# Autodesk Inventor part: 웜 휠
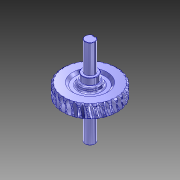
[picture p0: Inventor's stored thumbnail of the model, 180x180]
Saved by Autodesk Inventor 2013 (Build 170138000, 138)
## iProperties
Created: 2013-01
Part Number: 웜 휠
Material: 일반
Document SubType Name: Modeling
Designer: 한국산업디자인학원[gmhk.co.kr]
Categories: <?xml version="1.0" encoding="UTF-16"?> <MemberInstance><Categories><FamilyTemplate><FamilyTemplateParameter ValueType="xs:double" Id="1" ObjectReferenceKey="da
Density: 7.87 g/cm^3
Mass: 6989.44 g
Surface Area: 1041.74 cm^2
Volume: 888.112 cm^3
CustomPartVersion: 1
Author: 한국산업디자인학원[gmhk.co.kr]
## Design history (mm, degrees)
body "Solid1"
node "톱니 평면"
sketch "기본 본체 스케치"
  geometry: L1 (0, -14)-(0, 14) reference; L2 (0, 20)-(77.639, 20); L3 (77.639, 20)-(82.5, 15.652); L4 (-10, 0)-(60, 0) reference; L5 (82.5, 15.652)-(82.5, -15.652); L6 (0, -20)-(77.639, -20); L7 (0, 20)-(0, -20); L8 (77.639, -20)-(82.5, -15.652); C1 r 20 at (100, 0)
  constraints: 14 end point, 3 symmetric about line, 2 perpendicular, 2 point on line, 1 centre point, 1 collinear
  dimensions: "d50" = 41.8103 deg angle of L3 L2 (= da_fi); "d87" = 165 diameter of L5 L1 (= da_dae); "d89" = 40 diameter of C1 (= 2 x da_aw - da_da); "d92" = 40 distance of L2.start L6.start (= da_b); "d93" = 100 distance from line of C1.centre L7 (= da_aw)
revolve "기본 본체" stored, may be unused: angle "d35" = 90 deg
revolve "기본 본체2" stored, may be unused: angle "d90" = 90 deg
workplane "Work Plane13"
revolve "톱니" stored, may be unused: angle "d43" = 90 deg
pattern_circular "톱니 패턴" dims angle "d46" = 360 deg
workplane "Work Plane14"
workplane "Work Plane15"
revolve "회전6" stored, may be unused: angle "d97" = 90 deg
revolve "회전7" stored, may be unused: angle "d104" = 90 deg
fillet "모깎기1" dims "d105" = 5
chamfer "모따기1" distance "d106" = 1; stored, may be unused: second distance "d107" = 2, angle "d108" = 45 deg
node "작업 평면16"
sketch "스케치11"
  geometry: L1 (-14, 43)-(14, 43) reference; L2 (4, 43)-(4, 22); L3 (-4, 22)-(-4, 43); A1 r 4 centre (0, 22) between (-4, 22) and (4, 22); 2 further points
  constraints: 4 end point, 2 perpendicular, 2 point on circle, 2 point on line, 2 tangent, 1 centre point, 1 midpoint, 1 vertical alignment
  dimensions: "d109" = 8 distance between parallel lines of L2 L3; "d110" = 25 dimension on A1 L1
extrude "돌출1" cut sketch "스케치11" distance "d111" = 4; taper "d112" = 0 deg
mirror "대칭1"
sketch "톱니 스케치"
  geometry: L1 (10, 5.301)-(10, -5.301) reference; L2 (-32.842, 0)-(-12.948, 0) reference; L3 (-90, 6.896)-(-90, -6.896); L4 (-90, -6.896)-(-71, -6.896); L5 (-71, -6.896)-(-59, -2.529); L6 (-59, -2.529)-(-59, 0); L7 (-59, 2.529)-(-71, 6.896); L8 (-71, 6.896)-(-90, 6.896); L9 (-59, 2.529)-(-59, 0); L10 (-65, 0)-(-65, -4.712)
  constraints: 16 end point, 4 perpendicular, 3 equal length, 2 point on line, 1 midpoint, 1 parallel, 1 vertical
  dimensions: "d38" = 100 distance between parallel lines of L1 L3 (= da_aw); "d39" = 20 deg angle of L7 L8 (= da_alfat); "d40" = 19 distance of L7.end L3.start (= 0.5 x da_df1); "d41" = 25 distance between parallel lines of L3 L10 (= 0.5 x da_d1); "d42" = 4.71239 distance of L10.start L10.end (= 0.3 x da_px)
sketch "Sketch8"
  geometry: C1 r 77.639 at (0, 0) reference; C2 r 75 at (0, 0)
  constraints: 1 centre point, 1 coincident
  dimensions: "d77" = 150 diameter of C2 (= da_dw)
body "Srf1"
sketch "스케치9"
  geometry: L1 (-74.283, 20)-(-74.054, 20) reference; L2 (-74.054, 20)-(-74.261, 20) reference; L3 (-74.261, 20)-(-75.727, 20) reference; L4 (-77.355, 20)-(-75.727, 20) reference; L5 (-77.355, 20)-(-77.106, 20) reference; L6 (-77.106, 20)-(-76.222, 20) reference; L7 (-76.222, 20)-(-77.633, 20) reference; L8 (-77.045, 20)-(-77.633, 20) reference; L9 (-77.045, 20)-(-76.789, 20) reference; L10 (-76.789, 20)-(-74.852, 20) reference; L11 (-74.852, 20)-(-76.145, 20) reference; L12 (-73.369, 20)-(-76.145, 20) reference; L13 (-73.369, 20)-(-73.116, 20) reference; L14 (-73.116, 20)-(-70.211, 20) reference; L15 (-70.211, 20)-(-71.33, 20) reference; L16 (-66.486, 20)-(-71.33, 20) reference; L17 (-66.486, 20)-(-66.247, 20) reference; L18 (-66.247, 20)-(-62.501, 20) reference; L19 (-62.501, 20)-(-63.397, 20) reference; L20 (-56.697, 20)-(-63.397, 20) reference; L21 (-56.697, 20)-(-56.483, 20) reference; L22 (-56.483, 20)-(-52.059, 20) reference; L23 (-52.059, 20)-(-52.693, 20) reference; L24 (-44.431, 20)-(-52.693, 20) reference; L25 (-44.431, 20)-(-44.25, 20) reference; L26 (-44.25, 20)-(-39.342, 20) reference; L27 (-39.342, 20)-(-39.687, 20) reference; L28 (-30.222, 20)-(-39.687, 20) reference; L29 (-30.222, 20)-(-30.084, 20) reference; L30 (-30.084, 20)-(-24.906, 20) reference; L31 (-24.906, 20)-(-24.945, 20) reference; L32 (-14.693, 20)-(-24.945, 20) reference; L33 (-14.693, 20)-(-14.602, 20) reference; L34 (-14.602, 20)-(-9.381, 20) reference; L35 (-9.381, 20)-(-9.114, 20) reference; L36 (1.479, 20)-(-9.114, 20) reference; L37 (1.479, 20)-(1.517, 20) reference; L38 (1.517, 20)-(6.554, 20) reference; L39 (6.554, 20)-(7.116, 20) reference; L40 (17.586, 20)-(7.116, 20) reference; L41 (17.586, 20)-(17.571, 20) reference; L42 (17.571, 20)-(22.202, 20) reference; L43 (22.202, 20)-(23.034, 20) reference; L44 (32.924, 20)-(23.034, 20) reference; L45 (32.924, 20)-(32.856, 20) reference; L46 (32.856, 20)-(36.88, 20) reference; L47 (36.88, 20)-(37.946, 20) reference; L48 (46.823, 20)-(37.946, 20) reference; L49 (46.823, 20)-(46.705, 20) reference; L50 (46.705, 20)-(49.946, 20) reference; L51 (49.946, 20)-(51.2, 20) reference; L52 (58.676, 20)-(51.2, 20) reference; L53 (58.676, 20)-(58.514, 20) reference; L54 (58.514, 20)-(60.83, 20) reference; L55 (60.83, 20)-(62.216, 20) reference; L56 (67.965, 20)-(62.216, 20) reference; L57 (67.965, 20)-(67.764, 20) reference; L58 (67.764, 20)-(69.055, 20) reference; L59 (69.055, 20)-(70.512, 20) reference; L60 (74.283, 20)-(70.512, 20) reference; L61 (74.283, 20)-(74.054, 20) reference; L62 (74.054, 20)-(74.261, 20) reference; L63 (74.261, 20)-(75.727, 20) reference; L64 (77.355, 20)-(75.727, 20) reference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
  constraints: 8 end point, 3 point on line, 2 perpendicular, 1 parallel
  dimensions: "d94" = 90 diameter of L122.end L121; "d95" = 135 deg angle of L123 L122; "d96" = 13 distance from line of L121.start L122
node "투영된 루프1"
sketch "스케치10"
  geometry: L1 (45, 13)-(-45, 13) reference; L2 (0, 13)-(0, 133); L3 (0, 133)-(-15, 133); L4 (-15, 133)-(-15, 47); L5 (-15, 47)-(-22.5, 47); L6 (-22.5, 47)-(-22.5, 28); L7 (-22.5, 28)-(-30, 28); L8 (-30, 28)-(-30, 13); L9 (30, 47)-(-30, 47) reference; 1 further point
  constraints: 14 end point, 4 parallel, 3 perpendicular, 1 collinear, 1 midpoint, 1 point on line
  dimensions: "d99" = 30 diameter of L4 L2; "d100" = 45 diameter of L6 L2; "d101" = 60 diameter of L8 L2; "d102" = 15 distance between parallel lines of L7 L1; "d103" = 120 distance of L2.start L2.end
node "참조1"
feature "피치 지름" dims "d78" = 40 (= da_b), "d79" = 0
other parameters: "da_aw" = 100 [user parameter; used in 5 equation terms], "da_fi" = 41.8103 deg [user parameter; used in 1 equation term], "da_b" = 40 [user parameter; used in 2 equation terms], "da_df" = 138 [user parameter], "da_beta" = 1.97396 [user parameter; used in 1 equation term], "da_alfat" = 20 deg [user parameter; used in 1 equation term], "da_df1" = 38 [user parameter; used in 1 equation term], "da_px" = 90 deg [user parameter; used in 1 equation term], "d37" = -1.97396 (computed from da_rightdir, da_beta), "d69" = 0, "d73" = 0, "d75" = 6 deg (computed from da_z), "da_dw" = 150 [user parameter; used in 1 equation term], "da_rightdir" = 0 [user parameter; used in 1 equation term], "d80" = 0, "d81" = 0, "d82" = 0, "d83" = 6 deg (computed from da_z), "d84" = 0, "d85" = 180 deg, "da_dae" = 165 [user parameter; used in 1 equation term]
